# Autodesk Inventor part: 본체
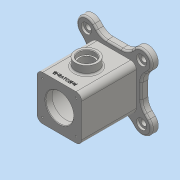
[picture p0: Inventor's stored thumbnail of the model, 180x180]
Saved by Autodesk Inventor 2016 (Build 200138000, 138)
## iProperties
Created: 2019-11
Part Number: 본체
Material: 일반
Document SubType Name: Modeling
Designer: user
Density: 1 g/cm^3
Appearance: 기본값
Mass: 398.027 g
Surface Area: 883.819 cm^2
Volume: 398.027 cm^3
Author: user
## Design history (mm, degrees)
sketch "스케치1"
  geometry: L1 (-49, 49)-(49, 49); L2 (49, 49)-(49, -49); L3 (49, -49)-(-49, -49); L4 (-49, -49)-(-49, 49); L5 (-49, 49)-(49, -49); L6 (49, 49)-(-49, -49); L7 (-49.497, 49.497)-(49.497, -49.497); L8 (-62.225, 36.77)-(36.77, -62.225); L9 (62.225, -36.77)-(-36.77, 62.225); L10 (-49.497, -49.497)-(49.497, 49.497); L11 (-36.77, -62.225)-(62.225, 36.77); L12 (36.77, 62.225)-(-62.225, -36.77); A1 r 18 centre (-49.497, 49.497) between (-36.77, 62.225) and (-62.225, 36.77); A2 r 18 centre (49.497, -49.497) between (36.77, -62.225) and (62.225, -36.77); A3 r 18 centre (-49.497, -49.497) between (-62.225, -36.77) and (-36.77, -62.225); A4 r 18 centre (49.497, 49.497) between (62.225, 36.77) and (36.77, 62.225); 1 further point
  constraints: 28 end point, 8 point on circle, 8 tangent, 4 centre point, 4 midpoint, 4 parallel, 2 point on line, 1 horizontal, 1 perpendicular
  dimensions: "d0" = 98 distance of L3.end L1.start; "d1" = 98 distance of L2.end L3.end; "d2" = 70 distance of point (0, 0) L7.end; "d3" = 36 diameter of A2; "d4" = 70 distance of point (0, 0) L10.end; "d5" = 36 diameter of A4
extrude "돌출1" new body sketch "스케치1" distance "d6" = 12; taper "d7" = 0 deg
fillet "모깎기1" dims "d8" = 25
sketch "스케치2"
  geometry: L1 (-40, -40)-(40, -40); L2 (40, -40)-(40, 40); L3 (40, 40)-(-40, 40); L4 (-40, 40)-(-40, -40); L5 (-40, -40)-(40, 40); L6 (40, -40)-(-40, 40); 1 further point
  constraints: 12 end point, 2 midpoint, 2 parallel, 1 horizontal, 1 perpendicular
  dimensions: "d9" = 80 distance of L2.end L3.end; "d10" = 80 distance of L1.end L2.end
extrude "돌출2" join sketch "스케치2" distance "d11" = 98; taper "d12" = 0 deg
sketch "스케치3"
  geometry: L1 (-40, -98)-(40, -98) reference; L2 (0, -98)-(0, 12); L3 (13.189, 12)-(-13.189, 12) reference; L4 (0, -98)-(-25, -98); L5 (-25, -98)-(-25, -86); L6 (-25, -86)-(-35, -86); L7 (-35, -86)-(-35, 0); L8 (-35, 0)-(-25, 0); L9 (-25, 0)-(-25, 12); L10 (-25, 12)-(0, 12); 1 further point
  constraints: 16 end point, 3 perpendicular, 3 point on line, 2 midpoint, 1 collinear, 1 vertical
  dimensions: "d13" = 12 distance between parallel lines of L6 L1; "d14" = 12 distance between parallel lines of L10 L8; "d15" = 70 diameter of L7 L2; "d16" = 50 diameter of L9 L2
revolve "회전1" sketch "스케치3" stored, may be unused: angle "d17" = 90 deg
sketch "스케치4"
  geometry: L1 (40, 40)-(40, -40) reference; L2 (0, 0)-(40, 40); L3 (0, 0)-(0, 30); L4 (0, 30)-(30, 30); 1 further point
  constraints: 6 end point, 1 coincident, 1 horizontal, 1 point on line, 1 vertical
  dimensions: "d18" = 30 distance of L2.start L3.end; "d19" = 30 distance of L3.end L4.end (derived)
hole "구멍1" sketch "스케치4" at (30, 30) diameter "d20" = 3.242; stored, may be unused: countersink angle "d24" = 90 deg, drill point angle "d26" = 118 deg; dims "d21" = 8, "d22" = 4, "d23" = 2, "d25" = 10
node "작업 평면1"
node "작업 평면2"
sketch "스케치5"
  geometry: L1 (-13.189, 12)-(13.189, 12) reference; C1 r 20 at (0, -49); 1 further point
  constraints: 1 centre point
  dimensions: "d34" = 40 diameter of C1; "d35" = 61 distance from line of C1.centre L1
extrude "돌출3" join sketch "스케치5" stored distance "d36" = 98; taper "d37" = 0 deg
sketch "스케치6"
  geometry: C1 r 20 at (0, 0) reference; 2 further points
  constraints: 1 coincident
hole "구멍2" sketch "스케치6" at (0, 0) diameter "d38" = 25; stored, may be unused: countersink angle "d42" = 90 deg, drill point angle "d44" = 118 deg; dims "d39" = 8, "d40" = 30, "d41" = 8, "d43" = 50
sketch "스케치7"
  geometry: A1 r 18 centre (49.497, 49.497) between (62.225, 36.77) and (36.77, 62.225) reference; 2 further points
  constraints: 1 coincident
hole "구멍3" sketch "스케치7" at (49.497, 49.497) diameter "d45" = 10; stored, may be unused: countersink angle "d49" = 90 deg, drill point angle "d51" = 118 deg; dims "d46" = 8, "d47" = 18, "d48" = 4, "d50" = 50
fillet "모깎기2" dims "d55" = 10
fillet "모깎기3" dims "d56" = 3
fillet "모깎기4" dims "d57" = 3
chamfer "모따기1" distance "d58" = 1; stored, may be unused: second distance "d59" = 2, angle "d60" = 45 deg
sketch "스케치8"
  geometry: L1 (60, -98)-(0, -98) reference; L2 (16.811, 0)-(43.189, 0) reference; 3 further points
  constraints: 1 midpoint, 1 vertical alignment, 1 other
  dimensions: "d61" = 10 distance from line of L1 point (30, -88)
feature "엠보싱1" sketch "스케치8" dims "d0" = 98, "d1" = 98, "d2" = 70, "d3" = 36, "d4" = 70, "d5" = 36, "d62" = 0.5, "d63" = 0
node "솔리드1"
pattern_linear "직사각형 패턴1" dims "d29" = 60
mirror "대칭1"
pattern_circular "원형 패턴1" dims angle "d53" = 360 deg
other parameters: "d33" = 55
